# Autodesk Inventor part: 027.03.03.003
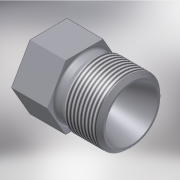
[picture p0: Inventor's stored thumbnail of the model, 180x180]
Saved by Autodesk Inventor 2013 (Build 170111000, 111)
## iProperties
Shininess: 64.0
Length Units: 11269
Angle Units: 11279
Time Units: 11290
Mass Units: 11283
Length Display Precision: 3
Angle Display Precision: 2
Created: 2003-06
Part Number: 027.03.03.003
Document SubType Name: Modeling
Designer: GSasha
Density: 1 g/cm^3
Material: Generic
Density: 0.0
Volumn: 0.0
Area: 0.0
PropertySet Name: Model Information
Control State: 0
Master: False
Checked Out: True
Checked Out Date: 2008-10-15
Last Check In Date: 2008-10-15
Author: GSasha
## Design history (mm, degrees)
sketch "Sketch1"
  geometry: L1 (-9.84, 0)-(-9.84, 23); L2 (-9.84, 23)-(5.16, 23); L3 (5.16, 23)-(5.16, 13.4); L4 (6.16, 12.4)-(8.232, 12.4); L5 (8.473, 12.462)-(10.36, 13.5); L6 (10.36, 13.5)-(23.56, 13.5); L7 (23.56, 13.5)-(25.16, 11.9); L8 (25.16, 11.9)-(25.16, 0); L9 (25.16, 0)-(-9.84, 0) reference; L10 (-9.84, 8.5)-(-4.84, 8.5); L11 (-4.84, 8.5)-(-4.84, 7); L12 (-4.84, 7)-(13.205, 7); L13 (13.205, 7)-(25.16, 11); A1 r 1 centre (6.16, 13.4) between (5.16, 13.4) and (6.16, 12.4); A2 r 0.5 centre (8.232, 12.9) between (8.232, 12.4) and (8.473, 12.462); 2 further points
  constraints: 26 end point, 7 parallel, 6 point on line, 4 point on circle, 4 tangent, 2 centre point, 2 perpendicular, 1 horizontal, 1 vertical
  dimensions: "d0" = 35 distance of L8.end L1.start; "d1" = 20 distance between parallel lines of L3 L8; "d2" = 45 deg angle of L7 L8; "d3" = 1.6 distance from line of L6.end L8; "d4" = 3.2 distance of point (5.16, 12.4) point (8.36, 12.4); "d5" = 5.2 distance from line of L5.end L3; "d6" = 13.5 distance between parallel lines of L6 L9; "d7" = 18.5 deg angle of L13 L9; "d8" = 11 distance from line of L13.end L9; "d9" = 7 distance between parallel lines of L12 L9; "d10" = 8.5 distance between parallel lines of L9 L10; "d11" = 5 distance between parallel lines of L11 L1; "d12" = 12.4 distance between parallel lines of L9 L4; "d13" = 1 radius of A1; "d14" = 0.5 radius of A2
revolve "Revolution1" sketch "Sketch1" stored, may be unused: angle "d15" = 90 deg
sketch "Sketch2"
  geometry: L1 (0, 15.588)-(13.5, 7.794); L2 (13.5, 7.794)-(13.5, -7.794); L3 (13.5, -7.794)-(0, -15.588); L4 (0, -15.588)-(-13.5, -7.794); L5 (-13.5, -7.794)-(-13.5, 7.794); L6 (-13.5, 7.794)-(0, 15.588); C1 r 23 at (0, 0) reference; 2 further points
  constraints: 12 end point, 1 coincident, 11 other
  dimensions: "d16" = 27 distance between parallel lines of L2 L5
extrude "Extrusion1" cut sketch "Sketch2" stored distance "d17" = 10; taper "d18" = 0 deg
feature "Резьба1" dims "d19" = 10, "d20" = 0
body "Solid1"
